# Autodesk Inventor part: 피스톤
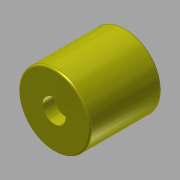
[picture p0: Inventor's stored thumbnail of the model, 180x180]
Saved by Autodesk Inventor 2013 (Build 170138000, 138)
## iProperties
Created: 2018-01
Part Number: 피스톤
Material: 강철, 탄소
Document SubType Name: Modeling
Designer: mduedu
Density: 7.87 g/cm^3
Mass: 44.9853 g
Surface Area: 21.9333 cm^2
Volume: 5.71605 cm^3
Author: mduedu
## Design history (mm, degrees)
sketch "스케치1"
  geometry: C1 r 10 at (0, 0); 1 further point
  constraints: 1 centre point, 1 coincident
  dimensions: "d0" = 20 diameter of C1
extrude "돌출1" new body sketch "스케치1" distance "d1" = 20; taper "d2" = 0 deg
hole "구멍1" diameter "d5" = 7; stored, may be unused: countersink angle "d9" = 90 deg, drill point angle "d11" = 0 deg; dims "d6" = 6, "d7" = 4, "d8" = 2, "d10" = 10, "d12" = 10, "d13" = 10
chamfer "모따기1" distance "d14" = 0.5; stored, may be unused: second distance "d15" = 2, angle "d16" = 45 deg
fillet "모깎기1" dims "d17" = 0.5
sketch "스케치2"
  geometry: 2 further points
  constraints: 1 coincident
sketch "스케치3"
  geometry: 2 further points
  constraints: 1 coincident
hole "구멍2" sketch "스케치3" at (0, 0) diameter "d18" = 3.4; stored, may be unused: countersink angle "d22" = 90 deg, drill point angle "d24" = 0 deg; dims "d19" = 6, "d20" = 6.5, "d21" = 3.4, "d23" = 8
node "솔리드1"
